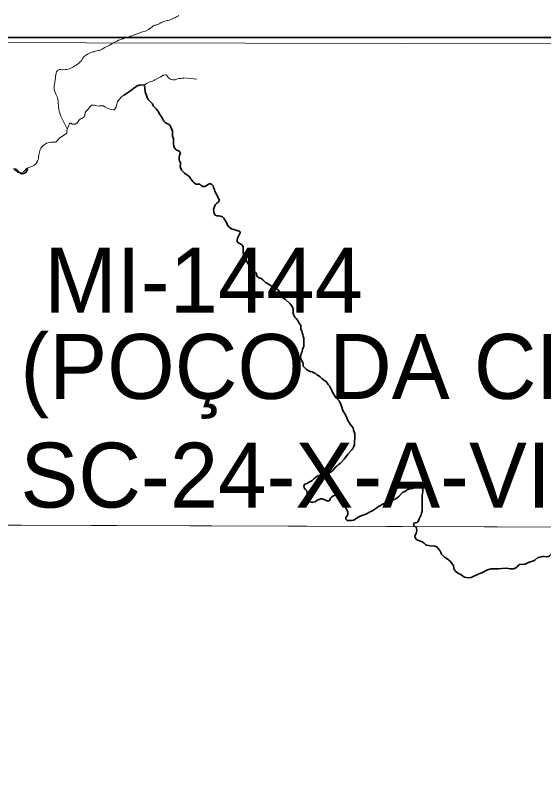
# Model space of a CAD drawing. Extents: x 553962 to 842807, y 8883888 to 9032388.
# Drawn here: x 589999 to 594066, y 8918990 to 8924940 of the extents above; entities that cross this region are included whole.
import ezdxf

# ---------------------------------------------------------------- set-up
doc = ezdxf.new("R2010")
doc.units = 0
doc.header["$LTSCALE"] = 200
doc.linetypes.add('LONG_DASH_SHORT_DASH', pattern=[9.9, 6, -1.2, 1.5, -1.2])
doc.layers.add('6', color=7, linetype='Continuous', lineweight=13)

msp = doc.modelspace()

# ---------------------------------------------------------------- linework, layer by layer
at = {"layer": '6'}
for points in [[(590344.7, 8924524.1), (590346.1, 8924523.9), (590358, 8924520.2), (590383.2, 8924523.4), (590393.5, 8924524), (590404.1, 8924526.7), (590414.4, 8924528.6), (590424.7, 8924532.6), (590445.3, 8924544.2), (590455.6, 8924551.2), (590465.9, 8924557), (590475.9, 8924563.2), (590484.8, 8924569.5), (590494.8, 8924578.4), (590504.2, 8924588.4), (590517, 8924609.5), (590517.1, 8924611), (590524.6, 8924619.7), (590534, 8924627.8), (590543.3, 8924634.2), (590554.6, 8924640.6), (590565.1, 8924647.2), (590585.7, 8924656.2), (590595.8, 8924658.8), (590606, 8924660.2), (590616.3, 8924664), (590626.7, 8924667.2), (590639.5, 8924669.1), (590642.4, 8924669.9), (590647.3, 8924670.5), (590657.6, 8924675), (590667.6, 8924678.8), (590688.5, 8924691.7), (590719.6, 8924707.4), (590729.6, 8924713.1), (590749.9, 8924725.7), (590758.9, 8924730.8), (590770.5, 8924736.7), (590781.1, 8924741.4), (590792, 8924748.1), (590801.7, 8924751.7), (590820, 8924755.7), (590820.5, 8924756.1), (590821.9, 8924758.3), (590825.7, 8924760.6), (590832.6, 8924762.1), (590837.2, 8924763.8), (590843.2, 8924768), (590853.2, 8924770.5), (590864.6, 8924772.2), (590873.8, 8924775), (590883, 8924778.7), (590894.4, 8924783.6), (590904.4, 8924787.2), (590916.9, 8924790.8), (590946.9, 8924800.3), (590957.5, 8924804.8), (590977.5, 8924812.4), (591000.1, 8924819.7), (591023.1, 8924830.1), (591026.5, 8924831.2), (591031.1, 8924835.4), (591044.3, 8924845.6), (591048.9, 8924850.1), (591053.2, 8924853.7), (591065.5, 8924862.8), (591073.3, 8924865.4), (591078.4, 8924865.6), (591082.8, 8924866), (591088.7, 8924867.5), (591094.1, 8924870.2), (591105.1, 8924874.4), (591108, 8924875.9), (591112, 8924879.1), (591116.6, 8924880.1), (591120.9, 8924882.9), (591124.8, 8924885), (591128.7, 8924888.2), (591133.8, 8924890.1), (591139, 8924892.5), (591169.3, 8924900.3), (591175.2, 8924901.1), (591185.6, 8924903.8), (591196.1, 8924907.8), (591205.7, 8924912.7), (591211.1, 8924915.9), (591216, 8924918.4), (591231.2, 8924922.4), (591232.2, 8924923.5), (591240.4, 8924928.8), (591244.5, 8924932.2), (591253.5, 8924937.3), (591256.3, 8924939.6)], [(590992.5, 8924408.9), (590998.2, 8924407.9), (591001.7, 8924410.6), (591009.4, 8924414.9), (591019.6, 8924420.2), (591029, 8924424.2), (591055.7, 8924433.9), (591064.4, 8924438.2), (591073.7, 8924444.1), (591099.9, 8924459.1), (591109.4, 8924462.7), (591118.2, 8924467), (591130.4, 8924475.9), (591134.9, 8924476.9), (591136.3, 8924478.6), (591137.1, 8924478.9), (591145.2, 8924480.7), (591162.1, 8924481.3), (591169.8, 8924470.2), (591176.4, 8924462.5), (591185.8, 8924454.4), (591193.6, 8924448.8), (591202.3, 8924445.7), (591211.4, 8924443.2), (591228.4, 8924443.3), (591248, 8924451.7), (591256.5, 8924453.6), (591265.2, 8924454.9), (591274.8, 8924454.9), (591289.2, 8924456.1), (591290.2, 8924456.7), (591292.7, 8924458.8), (591295.8, 8924459), (591395.2, 8924449.5)], [(590992.5, 8924402.1), (590990.2, 8924402.6), (590973.7, 8924404.6), (590952.7, 8924402.9), (590942.3, 8924398.3), (590932.8, 8924393.6), (590923, 8924387.5), (590914.7, 8924381.7), (590891.1, 8924363.9), (590882.9, 8924358.3), (590876.5, 8924353.5), (590862.7, 8924340.9), (590854.6, 8924335.8), (590835.3, 8924325.4), (590826.3, 8924319.7), (590818, 8924313.8), (590811.3, 8924307.8), (590800.4, 8924295.7), (590789.2, 8924281.4), (590785.1, 8924274.4), (590781.3, 8924266.7), (590778.8, 8924256.9), (590775.1, 8924237.1), (590773.8, 8924233.8), (590764.3, 8924217.2), (590758, 8924212.3), (590755.1, 8924211.9), (590738, 8924216), (590727.2, 8924217.6), (590721.5, 8924220.6), (590706.8, 8924226.4), (590696.7, 8924230.7), (590688.6, 8924236.5), (590677, 8924242.1), (590646.8, 8924242.2), (590635.5, 8924241.6), (590625.2, 8924242.9), (590604.8, 8924247.7), (590590, 8924247.6), (590588.5, 8924247.4), (590574.8, 8924237.1), (590556.4, 8924214), (590548.1, 8924207.6), (590540.8, 8924200.3), (590539, 8924198), (590538.7, 8924197.1), (590538.5, 8924194.4), (590536.1, 8924190.7), (590534.2, 8924168.1), (590532.4, 8924165.1), (590530.3, 8924164.5), (590527.7, 8924157.9), (590523.1, 8924155.6), (590510, 8924144.5), (590501.7, 8924142.9), (590490.8, 8924134.1), (590489.8, 8924130.3), (590488.1, 8924129.4), (590477.2, 8924114.8), (590471.2, 8924109.6), (590459.3, 8924102), (590457.6, 8924101.6), (590440.8, 8924101.2), (590440.2, 8924101.4), (590439, 8924102.9), (590436.2, 8924103), (590432, 8924105.7), (590431, 8924107.3), (590427.5, 8924108.1), (590425.4, 8924110.3), (590416, 8924109.2), (590415.1, 8924105.6), (590413, 8924103.7), (590412.7, 8924103.2), (590411.1, 8924087.9), (590397.2, 8924064.7)], [(590397.2, 8924064.7), (590397.2, 8924064.7), (590389.6, 8924081.3), (590384.3, 8924092), (590380.2, 8924102.3), (590374.6, 8924112.4), (590369.9, 8924122.8), (590352.7, 8924153), (590347.6, 8924162.9), (590342.2, 8924179.5), (590338.2, 8924194.3), (590335, 8924204.5), (590332.3, 8924215.2), (590331, 8924235.1), (590330.9, 8924245.8), (590328.3, 8924265.8), (590328.2, 8924276.7), (590325.6, 8924296.8), (590322, 8924307.9), (590312.8, 8924329.1), (590304.5, 8924346.2)], [(589991.2, 8923749.3), (590013.6, 8923734.5), (590015.6, 8923732.4), (590018, 8923732.1), (590018.8, 8923730), (590019.5, 8923729.4), (590040.4, 8923724.8), (590041.7, 8923725), (590051, 8923729.2), (590060.6, 8923735), (590068.8, 8923742.4), (590083.2, 8923761.2), (590093.2, 8923765), (590103.7, 8923768.5), (590113.7, 8923772.2), (590124.3, 8923774.9), (590141.8, 8923783.6), (590149.8, 8923790.2), (590155.1, 8923795.5), (590162.2, 8923804.2), (590168.8, 8923815.7), (590172.5, 8923825.7), (590175.5, 8923835.3), (590175.7, 8923846.6), (590178.2, 8923866.7), (590185.8, 8923897.6), (590188.8, 8923907.7), (590194.8, 8923917.5), (590200.8, 8923925.8), (590210.7, 8923934.5), (590238.8, 8923955.5), (590271.9, 8923963.9), (590292.3, 8923963.9), (590306.4, 8923963.4), (590312, 8923965.1), (590320.8, 8923973.6), (590326.7, 8923981.9), (590333.3, 8923989.3), (590341.6, 8923996.5), (590361.1, 8924009.5), (590378.2, 8924022.2), (590391.5, 8924031), (590393.5, 8924037.1), (590394.6, 8924044), (590393.9, 8924046.5), (590397.1, 8924063), (590397.2, 8924064.7)], [(574684.9, 8921064.7), (596639.8, 8920989.8), (607636.3, 8920937.2), (626625.7, 8920820.5)]]:
    msp.add_lwpolyline(points, dxfattribs=at)
at = {"layer": '6', "lineweight": 35}
msp.add_lwpolyline([(574695.3, 8924769.6), (626625.7, 8924769.6), (626625.7, 8896026.7), (574695.3, 8896026.7)], close=True, dxfattribs=at)
at = {"layer": '6'}
msp.add_lwpolyline([(585656.3, 8924738.8), (596655.5, 8924715.8), (596639.8, 8920989.8), (585645.8, 8921027.3)], close=True, dxfattribs=at)
at = {"layer": '6', "linetype": 'LONG_DASH_SHORT_DASH', "lineweight": 35}
for points in [[(591402.7, 8923639.7), (591389.2, 8923638.7), (591375.1, 8923649.2), (591364.5, 8923660.2), (591355.4, 8923672.7), (591347.8, 8923684.2), (591338.7, 8923695.2), (591325.6, 8923706.7), (591312, 8923715.7), (591300.9, 8923724.2), (591287.3, 8923736.1), (591278.2, 8923748.7), (591268.1, 8923776.2), (591269, 8923791.8), (591271, 8923805.9), (591262.4, 8923816.9), (591258.8, 8923831.9), (591259.3, 8923848.5), (591263.2, 8923863.1), (591270.2, 8923876.2), (591263.1, 8923890.2), (591249, 8923899.2), (591235.9, 8923905.1), (591223.3, 8923918.6), (591218.8, 8923932.2), (591215.7, 8923949.2), (591215.6, 8923980.3), (591215, 8923993.9), (591208.4, 8924006.9), (591208.3, 8924035.1), (591207.3, 8924048.6), (591203.2, 8924062.6), (591196.1, 8924075.7), (591191.5, 8924091.7), (591177.4, 8924102.2), (591164.8, 8924107.7), (591152.8, 8924115.7), (591142.7, 8924126.2), (591133.1, 8924139.7), (591123.5, 8924157.2), (591105.3, 8924183.2), (591099.7, 8924195.8), (591092.1, 8924207.3), (591082, 8924219.3), (591070.4, 8924231.8), (591060.8, 8924243.8), (591054.8, 8924257.8), (591041.6, 8924270.3), (591021.5, 8924292.8), (591012.4, 8924307.9), (591008.8, 8924321.9), (590998.8, 8924350.2), (590992.5, 8924403.6), (590959.8, 8924405.2), (590935.8, 8924396.5), (590908.7, 8924376.5), (590878.4, 8924353.4), (590830.6, 8924322.3)], [(590095.4, 8923759.3), (590091.6, 8923755.2), (590086.2, 8923742.6), (590078.2, 8923729), (590063.1, 8923721.9), (590045.5, 8923720.3), (590031.9, 8923727.8), (590011.7, 8923748.3), (590000.2, 8923755.8), (589984.1, 8923756.7)], [(591592.6, 8923388.5), (591579, 8923392.4), (591563.9, 8923394.4), (591549.9, 8923394.8), (591537.8, 8923401.8), (591529.7, 8923412.8), (591525.6, 8923429.9), (591525.1, 8923445.4), (591529, 8923458.5), (591534, 8923471.6), (591540.5, 8923483.7), (591551, 8923493.7), (591563, 8923503.3), (591569.5, 8923515.9), (591562.4, 8923528.9), (591555.8, 8923543.5), (591550.8, 8923557.5), (591542.2, 8923569.5), (591535.6, 8923584.1), (591531.5, 8923598.6), (591525.4, 8923613.6), (591521.4, 8923627.7), (591511.3, 8923637.2), (591495.7, 8923643.6), (591482.6, 8923636.6), (591471.1, 8923628), (591458.1, 8923620.9), (591442, 8923621.3), (591428.9, 8923629.8), (591417.8, 8923640.3), (591402.7, 8923639.7)], [(592179.5, 8922576.1), (592172.9, 8922589.1), (592160.3, 8922603.6), (592151.7, 8922615.6), (592144.1, 8922629.2), (592137.5, 8922646.7), (592137.4, 8922676.8), (592133.8, 8922692.4), (592126.2, 8922705.9), (592114.1, 8922717.9), (592078.8, 8922751.4), (592064.7, 8922758.4), (592052.6, 8922765.8), (592039.5, 8922776.8), (592035, 8922789.9), (592032.9, 8922803.4), (592027.8, 8922819), (592016.2, 8922828.9), (592004.6, 8922837.4), (591990, 8922845.9), (591964.4, 8922857.8), (591938.7, 8922876.3), (591925.1, 8922882.8), (591914, 8922892.8), (591903.9, 8922902.8), (591890.8, 8922911.8), (591876.2, 8922917.2), (591862.6, 8922925.2), (591855, 8922937.2), (591855, 8922953.8), (591844.4, 8922963.3), (591830.8, 8922966.7), (591826.7, 8922982.8), (591817.2, 8922992.8), (591804.6, 8922998.2), (591798.5, 8923010.8), (591793.9, 8923023.8), (591784.8, 8923036.3), (591777.7, 8923051.9), (591770.2, 8923063.9), (591763.6, 8923079.4), (591756.5, 8923094.9), (591752.9, 8923111.5), (591752.8, 8923140.6), (591752.2, 8923155.7), (591745.2, 8923169.2), (591733.1, 8923180.2), (591719.5, 8923184.7), (591707.4, 8923194.2), (591705.8, 8923209.2), (591709.3, 8923222.8), (591722.8, 8923248.9), (591729.2, 8923264), (591727.2, 8923277.6), (591712.1, 8923280), (591697, 8923284), (591684.4, 8923289.5), (591666.8, 8923292.9), (591654.2, 8923299.9), (591641.6, 8923310.4), (591633, 8923323.4), (591627.5, 8923337.9), (591612.8, 8923366), (591602.7, 8923378), (591592.6, 8923388.5)], [(592253.2, 8922202.8), (592237.1, 8922214.8), (592224.5, 8922226.3), (592215.4, 8922237.8), (592214.8, 8922251.9), (592213.3, 8922266.4), (592204.7, 8922278.9), (592196.1, 8922292.5), (592195.5, 8922307), (592197, 8922320.6), (592200.5, 8922334.7), (592205.9, 8922350.8), (592209.9, 8922365.3), (592215.4, 8922378.4), (592219.3, 8922391.5), (592220.3, 8922405.6), (592220.1, 8922452.2), (592215.5, 8922466.8), (592212, 8922481.8), (592205.9, 8922494.4), (592203.8, 8922508.9), (592196.8, 8922520.9), (592195.7, 8922536), (592195.6, 8922551.6), (592179.5, 8922576.1)], [(592243.9, 8921333.6), (592256.4, 8921341.1), (592270.4, 8921349.2), (592284, 8921355.8), (592296.5, 8921368.4), (592308.5, 8921379.5), (592322, 8921388.6), (592338.6, 8921394.2), (592352.2, 8921397.8), (592399.8, 8921408.1), (592415.4, 8921413.7), (592430, 8921422.3), (592443.5, 8921433.4), (592454, 8921445.5), (592464.5, 8921459.1), (592476.5, 8921470.2), (592487.5, 8921478.3), (592499.5, 8921488.4), (592531.6, 8921520.6), (592558.1, 8921558.9), (592589.6, 8921591.7), (592598.1, 8921603.3), (592605.1, 8921618.4), (592609, 8921636.5), (592610, 8921653.1), (592612.4, 8921684.7), (592612.3, 8921702.8), (592611.7, 8921717.8), (592607.2, 8921730.9), (592603.1, 8921743.9), (592599, 8921761), (592587.9, 8921777), (592576.8, 8921790.5), (592568.2, 8921803.5), (592557.6, 8921817.5), (592552.5, 8921832.6), (592548.5, 8921846.1), (592540.9, 8921860.6), (592534.8, 8921873.7), (592525.7, 8921886.2), (592518.6, 8921903.2), (592512.5, 8921920.8), (592507.9, 8921936.3), (592500.3, 8921955.4), (592491.7, 8921968.9), (592481.6, 8921980.9), (592471, 8921990.9), (592461.5, 8922003.4), (592443.3, 8922031.9), (592437.2, 8922044.5), (592431.1, 8922060.5), (592424, 8922072.5), (592417.9, 8922086.6), (592407.8, 8922097.1), (592391.2, 8922120.1), (592374.6, 8922130.6), (592358.9, 8922141), (592345.3, 8922154), (592334.7, 8922163), (592321.2, 8922170.5), (592309.6, 8922181), (592296, 8922186.4), (592284.4, 8922194.4), (592268.8, 8922197.4), (592253.2, 8922202.8)], [(592506, 8921239.8), (592476.8, 8921242.7), (592462.3, 8921242.1), (592448.7, 8921239.1), (592434.7, 8921230.9), (592426.2, 8921220.4), (592419.7, 8921204.3), (592407.2, 8921196.2), (592391.1, 8921201.6), (592364.4, 8921215.6), (592348.8, 8921216), (592336.8, 8921208.9), (592322.2, 8921203.8), (592308.2, 8921192.7), (592290.1, 8921189.6), (592276.1, 8921189.6), (592260.5, 8921193), (592248.4, 8921202.5), (592247.3, 8921216.1), (592246.7, 8921233.1), (592246.7, 8921247.2), (592246.1, 8921260.7), (592242.1, 8921276.3), (592231.5, 8921287.8), (592222.9, 8921299.3), (592219.3, 8921315.4), (592228.8, 8921326.9), (592243.9, 8921333.6)], [(593074.3, 8921000.4), (593067.1, 8921009.3), (593064.5, 8921023.9), (593077.6, 8921029.5), (593092.1, 8921033), (593104.1, 8921044.7), (593108.1, 8921061.2), (593114.6, 8921076.3), (593123, 8921091.4), (593127, 8921105), (593130, 8921120.6), (593130.9, 8921135.7), (593131.8, 8921165.8), (593131.5, 8921240.1), (593135.9, 8921272.3), (593136.9, 8921285.8), (593131.3, 8921299.9), (593117.7, 8921303.8), (593102.1, 8921303.8), (593089.1, 8921299.2), (593074.5, 8921298.6), (593057.5, 8921295), (593038.4, 8921292.9), (593020.8, 8921285.8), (593007.8, 8921279.7), (592997.3, 8921271.1), (592982.7, 8921265.1), (592971.7, 8921255.5), (592951.2, 8921233.8), (592939.2, 8921223.7), (592928.1, 8921215.6), (592915.1, 8921210), (592900.1, 8921201.4), (592881.5, 8921197.8), (592854.4, 8921188.7), (592837.8, 8921178.5), (592824.8, 8921172.9), (592809.8, 8921163.3), (592795.2, 8921155.2), (592781.7, 8921146.1), (592767.7, 8921135), (592751.6, 8921125.4), (592719.5, 8921109.2), (592708, 8921101.1), (592692, 8921094), (592673.4, 8921089.9), (592644.3, 8921077.2), (592615.7, 8921059), (592602.2, 8921051.9), (592586.1, 8921047.8), (592571.5, 8921047.3), (592554.9, 8921049.2), (592543.9, 8921057.2), (592544.3, 8921072.8), (592554.8, 8921082.3), (592557.8, 8921096.9), (592557.7, 8921112), (592553.6, 8921128), (592543.5, 8921143.6), (592537.5, 8921158.1), (592533.9, 8921172.6), (592530.3, 8921189.2), (592525.7, 8921217.3), (592518.1, 8921231.3), (592506, 8921239.8)], [(593082.3, 8921002.1), (593088.7, 8920987.9), (593089.8, 8920968), (593084.4, 8920948.3), (593076.2, 8920935.2), (593075, 8920930.6), (593075.9, 8920921.5), (593084.8, 8920903), (593091.1, 8920899.2), (593119.5, 8920888.7)], [(593119.5, 8920888.7), (593131.8, 8920884.2), (593147.7, 8920872.4), (593160.1, 8920860.8), (593166.7, 8920857.9), (593192.6, 8920851.8), (593227.7, 8920849.4), (593243.1, 8920843.9), (593266.9, 8920816.1), (593275.7, 8920802), (593280.1, 8920789), (593284.9, 8920782.6), (593304.2, 8920765.5), (593322.5, 8920752.4)], [(594030.9, 8920764), (594054.9, 8920770.3), (594073.9, 8920770.6), (594092, 8920768.1), (594103, 8920771.6), (594111.8, 8920776.3), (594138.2, 8920802.2), (594156.9, 8920817.3), (594159.3, 8920821.2), (594159, 8920825), (594150, 8920833.8), (594150.8, 8920840.9), (594161, 8920850.4), (594174.3, 8920856.6), (594180.7, 8920861.6), (594187.3, 8920871.1), (594189.3, 8920877.9), (594182.3, 8920894.6), (594176.2, 8920899.4)], [(593322.5, 8920752.4), (593347.4, 8920734.5), (593372.7, 8920702.2), (593373.5, 8920692.7)], [(593845.9, 8920680.4), (593849, 8920681.9), (593862.8, 8920691.4), (593874.2, 8920704.1), (593881.4, 8920709.6), (593921.2, 8920712.4), (593929.8, 8920715), (593950, 8920724.9), (593989.6, 8920737.7), (593999.3, 8920743.2), (594022.2, 8920761.7), (594030.9, 8920764)], [(593373.5, 8920692.7), (593374.2, 8920684.6), (593377, 8920671.6), (593390.5, 8920655.4), (593406.8, 8920642.9), (593428.8, 8920631.4), (593444, 8920618.6), (593456, 8920611.2), (593471.5, 8920608.3)], [(593591.1, 8920645.9), (593634.1, 8920668.6), (593661.5, 8920676.8), (593719.8, 8920675.5), (593745.2, 8920679.2), (593781.7, 8920682), (593808.2, 8920676), (593827.3, 8920675.2), (593837.8, 8920676.5), (593845.9, 8920680.4)], [(593471.5, 8920608.3), (593486.6, 8920605.5), (593509.7, 8920608.3), (593567, 8920636.9), (593591.1, 8920645.9)]]:
    msp.add_lwpolyline(points, dxfattribs=at)
at = {"layer": '6'}
msp.add_spline([(590304.5, 8924346.2), (590297.2, 8924376.4), (590301.6, 8924419.9), (590308.1, 8924468.9), (590323.3, 8924514.7), (590344.7, 8924524.1)], degree=3, dxfattribs=at)

# ---------------------------------------------------------------- texts
for s, p in [('MI-1444', (590221.3, 8922649.4)), ('(POÇO DA CRUZ)', (590036.9, 8921984.9)), ('SC-24-X-A-VI', (590036.9, 8921147.9))]:
    msp.add_text(s, height=500, dxfattribs=at).set_placement(p)

doc.saveas('drawing.dxf')
